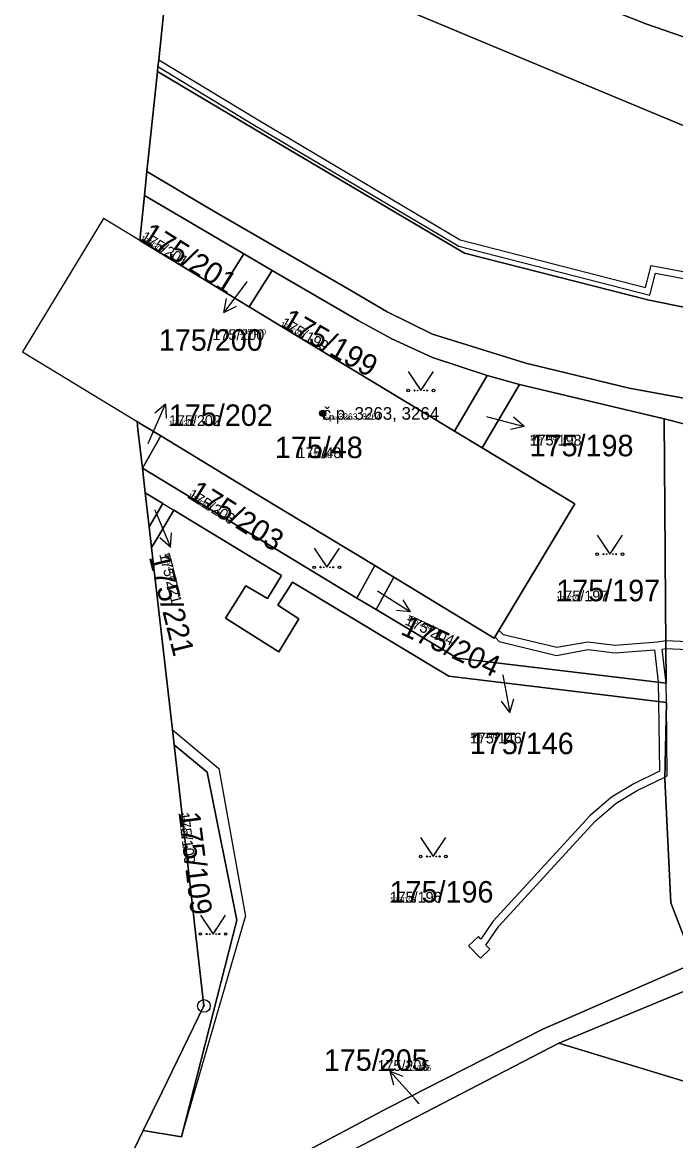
# Model space of a CAD drawing. Extents: x -759873 to -758487, y -975024 to -973516.
# Drawn here: x -759757.9 to -759706.2, y -974666.3 to -974577.8 of the extents above; entities that cross this region are included whole.
import ezdxf

# ---------------------------------------------------------------- set-up
doc = ezdxf.new("R2010")
doc.units = 0
for name, color, linetype in [('KAT_01_hranice KU', 7, 'Continuous'), ('KAT_02_hranice parcel', 7, 'Continuous'), ('KAT_03_1000_st čísla parcelní', 7, 'Continuous'), ('KAT_03_1000_čísla parcelní', 7, 'Continuous'), ('KAT_03_1000_čísla popisná', 7, 'Continuous'), ('KAT_03_250_st čísla parcelní', 7, 'Continuous'), ('KAT_03_250_čísla parcelní', 7, 'Continuous'), ('KAT_03_250_čísla popisná', 7, 'Continuous'), ('KAT_03_500_st čísla parcelní', 7, 'Continuous'), ('KAT_03_500_čísla parcelní', 7, 'Continuous'), ('KAT_03_500_čísla popisná', 7, 'Continuous'), ('KAT_04_vnitřní kresba', 7, 'Continuous'), ('KAT_05_1000_značky kultur', 7, 'Continuous'), ('KAT_05_250_značky kultur', 7, 'Continuous'), ('KAT_05_500_značky kultur', 7, 'Continuous'), ('KAT_07_1000_značky budov', 7, 'Continuous'), ('KAT_07_250_značky budov', 7, 'Continuous'), ('KAT_07_500_značky budov', 7, 'Continuous'), ('KAT_10_věcná břemena', 7, 'Continuous'), ('KAT_11_značky bodu BP', 7, 'Continuous'), ('KAT_12_pomocná šipka', 7, 'Continuous'), ('KAT_14_plocha_budovy', 7, 'Continuous'), ('KAT_14_plocha_pozemek', 7, 'Continuous')]:
    doc.layers.add(name, color=color, linetype=linetype)

msp = doc.modelspace()

# ---------------------------------------------------------------- linework, layer by layer
at = {"layer": 'KAT_01_hranice KU'}
msp.add_lwpolyline([(-759745.87, -974569.1), (-759747.08, -974580.72), (-759747.14, -974581.27), (-759747.18, -974581.65), (-759748.01, -974589.58), (-759748.21, -974591.46), (-759748.58, -974595.04), (-759751.46, -974593.29), (-759757.87, -974603.85), (-759748.79, -974609.36), (-759748.72, -974610), (-759748.37, -974613.06), (-759748.14, -974615.02), (-759747.83, -974617.71), (-759747.65, -974619.33), (-759746, -974633.78), (-759745.86, -974634.95), (-759743.5, -974655.62), (-759746.84, -974662.48), (-759747.59, -974664.02), (-759748.3, -974665.48), (-759749.65, -974668.28)], dxfattribs=at)
at = {"layer": 'KAT_02_hranice parcel'}
for p, q in [((-759748.01, -974589.58), (-759747.18, -974581.65)), ((-759748.21, -974591.46), (-759748.01, -974589.58)), ((-759748.58, -974595.04), (-759748.21, -974591.46)), ((-759748.21, -974591.46), (-759740.34, -974596.08)), ((-759751.46, -974593.29), (-759757.87, -974603.85)), ((-759748.58, -974595.04), (-759751.46, -974593.29)), ((-759742.14, -974598.94), (-759748.58, -974595.04)), ((-759740.34, -974596.08), (-759742.14, -974598.94)), ((-759740.34, -974596.08), (-759738.11, -974597.4)), ((-759738.11, -974597.4), (-759739.92, -974600.29)), ((-759739.92, -974600.29), (-759742.14, -974598.94)), ((-759757.87, -974603.85), (-759748.79, -974609.36)), ((-759721.07, -974605.73), (-759723.67, -974610.12)), ((-759718.53, -974606.42), (-759721.49, -974611.44)), ((-759721.07, -974605.73), (-759718.53, -974606.42)), ((-759718.53, -974606.42), (-759707.06, -974609.14)), ((-759707.06, -974609.14), (-759705.42, -974609.56)), ((-759748.37, -974613.06), (-759746.92, -974610.5)), ((-759721.49, -974611.44), (-759723.67, -974610.12)), ((-759731.41, -974623.34), (-759748.37, -974613.06)), ((-759748.14, -974615.02), (-759748.37, -974613.06)), ((-759747.83, -974617.71), (-759748.14, -974615.02)), ((-759747.65, -974619.33), (-759747.83, -974617.71)), ((-759746, -974633.78), (-759747.65, -974619.33)), ((-759731.41, -974623.34), (-759729.98, -974620.77)), ((-759729.98, -974620.77), (-759728.46, -974621.69)), ((-759728.46, -974621.69), (-759729.87, -974624.24)), ((-759729.87, -974624.24), (-759731.41, -974623.34)), ((-759745.86, -974634.95), (-759746, -974633.78)), ((-759702.4, -974662.54), (-759715.4, -974658.58)), ((-759749.65, -974668.28), (-759748.3, -974665.48))]:
    msp.add_line(p, q, dxfattribs=at)
for points in [[(-759745.19, -974562.55), (-759740.43, -974566.11), (-759725.32, -974571.2), (-759708.52, -974577.87), (-759697.61, -974581.66), (-759664.15, -974586.53), (-759642.54, -974589.75), (-759622.82, -974591), (-759601.22, -974591.07), (-759588.97, -974591.35), (-759580.29, -974589.86), (-759566.46, -974586.39), (-759552.88, -974583.63), (-759547.64, -974583.57)], [(-759747.18, -974581.65), (-759747.14, -974581.27), (-759747.08, -974580.72), (-759745.87, -974569.1)], [(-759745.87, -974569.1), (-759700, -974588.25), (-759649.5, -974597.3), (-759602.4, -974597), (-759547.6, -974592.2), (-759547.08, -974592.24)], [(-759747.18, -974581.65), (-759739.5, -974586.23), (-759722.87, -974596.03), (-759708.27, -974599.76), (-759702.25, -974600.96), (-759687.1, -974602.03), (-759663.8, -974603.29), (-759645.06, -974604.23), (-759636.24, -974604.67), (-759636.23, -974604.2), (-759636.16, -974602.4), (-759636.52, -974602.38), (-759636.5, -974601.88), (-759636.4, -974600.27), (-759636.59, -974600.26), (-759636.49, -974598.18), (-759625.38, -974598.56), (-759610.38, -974599.11), (-759596.55, -974599.59)], [(-759748.01, -974589.58), (-759742.78, -974592.68), (-759732.01, -974598.91), (-759728.99, -974600.68), (-759725.4, -974602.45), (-759718.02, -974604.75), (-759709.84, -974606.71), (-759702.63, -974608.03), (-759689.82, -974608.95), (-759677.23, -974609.87), (-759664.06, -974610.49), (-759641.64, -974611.43), (-759620.48, -974612.36), (-759598.5, -974613.15), (-759577.03, -974613.93), (-759558.28, -974614.4), (-759534.22, -974615.1), (-759512.72, -974615.61), (-759490.5, -974616.02), (-759471.82, -974616.25), (-759458.92, -974616), (-759446.09, -974615.46)], [(-759738.11, -974597.4), (-759731.29, -974601.36), (-759728.62, -974602.81), (-759725.41, -974604.3), (-759721.07, -974605.73)], [(-759723.67, -974610.12), (-759732.79, -974604.61), (-759739.92, -974600.29)], [(-759707.06, -974609.14), (-759707, -974619.81), (-759706.96, -974623.84), (-759706.91, -974630.08), (-759723.46, -974628.1), (-759729.87, -974624.24)], [(-759748.79, -974609.36), (-759748.47, -974609.56), (-759746.92, -974610.5)], [(-759748.37, -974613.06), (-759748.72, -974610), (-759748.79, -974609.36)], [(-759746.92, -974610.5), (-759739.2, -974615.18), (-759729.98, -974620.77)], [(-759728.46, -974621.69), (-759720.53, -974626.5), (-759714.13, -974615.89), (-759721.49, -974611.44)], [(-759748.14, -974615.02), (-759746.75, -974615.85), (-759747.83, -974617.71)], [(-759747.65, -974619.33), (-759747.18, -974618.58), (-759745.89, -974616.37), (-759737.35, -974621.56), (-759738.48, -974623.37), (-759740.17, -974622.36), (-759741.79, -974624.94), (-759737.57, -974627.58), (-759735.99, -974624.98), (-759737.64, -974623.91), (-759736.49, -974622.08), (-759724.11, -974629.53), (-759706.9, -974631.61), (-759707.03, -974637.67), (-759706.54, -974647.47), (-759704.69, -974652.23)], [(-759748.3, -974665.48), (-759745.28, -974665.99), (-759740.9, -974648.84), (-759743.24, -974637.11), (-759745.86, -974634.95)], [(-759746.84, -974662.48), (-759743.5, -974655.62), (-759745.86, -974634.95)], [(-759715.4, -974658.58), (-759700.76, -974652.49), (-759684.23, -974647.96), (-759662.52, -974646.3), (-759662.17, -974641.26), (-759630.55, -974642.48), (-759594.91, -974643.96), (-759576.85, -974644.52), (-759577.12, -974649.37), (-759571.57, -974649.69)], [(-759747.95, -974673.79), (-759728.92, -974663.7), (-759716.68, -974657.46), (-759704.69, -974652.23)], [(-759715.4, -974658.58), (-759733.05, -974667.73), (-759745.1, -974674.23), (-759747.28, -974674.58), (-759747.95, -974673.79)], [(-759748.3, -974665.48), (-759747.59, -974664.02), (-759746.84, -974662.48)]]:
    msp.add_lwpolyline(points, dxfattribs=at)
at = {"layer": 'KAT_03_1000_čísla popisná'}
msp.add_circle((-759734.1, -974608.72), 0.25, dxfattribs=at)
at = {"layer": 'KAT_03_250_čísla popisná'}
msp.add_circle((-759734.1, -974608.72), 0.0625, dxfattribs=at)
at = {"layer": 'KAT_03_500_čísla popisná'}
msp.add_circle((-759734.1, -974608.72), 0.125, dxfattribs=at)
at = {"layer": 'KAT_04_vnitřní kresba'}
for p, q in [((-759747.08, -974580.72), (-759739.22, -974585.49)), ((-759747.14, -974581.27), (-759739.48, -974585.92)), ((-759739.48, -974585.92), (-759723.33, -974595.47)), ((-759739.22, -974585.49), (-759723.21, -974594.99)), ((-759723.21, -974594.99), (-759708.56, -974598.76)), ((-759723.33, -974595.47), (-759708.2, -974599.37)), ((-759708.56, -974598.76), (-759708.11, -974597.02)), ((-759708.2, -974599.37), (-759707.75, -974597.63)), ((-759708.11, -974597.02), (-759701.56, -974598.24)), ((-759707.75, -974597.63), (-759702.1, -974598.7)), ((-759746.75, -974615.85), (-759745.89, -974616.37)), ((-759746, -974633.78), (-759742.32, -974636.83)), ((-759742.32, -974636.83), (-759740.21, -974648.55)), ((-759745.28, -974665.99), (-759740.21, -974648.55))]:
    msp.add_line(p, q, dxfattribs=at)
at = {"layer": 'KAT_05_1000_značky kultur'}
for points in [[(-759727.33, -974605.409), (-759726.33, -974606.91), (-759725.33, -974605.409)], [(-759712.37, -974618.359), (-759711.37, -974619.86), (-759710.37, -974618.359)], [(-759734.77, -974619.399), (-759733.77, -974620.9), (-759732.77, -974619.399)], [(-759726.35, -974642.289), (-759725.35, -974643.79), (-759724.35, -974642.289)], [(-759743.78, -974648.429), (-759742.78, -974649.93), (-759741.78, -974648.429)]]:
    msp.add_lwpolyline(points, dxfattribs=at)
for centre in [(-759727.33, -974606.909), (-759725.33, -974606.909), (-759712.37, -974619.859), (-759710.37, -974619.859), (-759734.77, -974620.899), (-759732.77, -974620.899), (-759726.35, -974643.789), (-759724.35, -974643.789), (-759743.78, -974649.929), (-759741.78, -974649.929)]:
    msp.add_circle(centre, 0.1, dxfattribs=at)
at = {"layer": 'KAT_05_250_značky kultur'}
for points in [[(-759726.58, -974606.535), (-759726.33, -974606.91), (-759726.08, -974606.535)], [(-759711.62, -974619.485), (-759711.37, -974619.86), (-759711.12, -974619.485)], [(-759734.02, -974620.525), (-759733.77, -974620.9), (-759733.52, -974620.525)], [(-759725.6, -974643.415), (-759725.35, -974643.79), (-759725.1, -974643.415)], [(-759743.03, -974649.555), (-759742.78, -974649.93), (-759742.53, -974649.555)]]:
    msp.add_lwpolyline(points, dxfattribs=at)
for centre in [(-759726.58, -974606.91), (-759726.08, -974606.91), (-759711.62, -974619.86), (-759711.12, -974619.86), (-759734.02, -974620.9), (-759733.52, -974620.9), (-759725.6, -974643.79), (-759725.1, -974643.79), (-759743.03, -974649.93), (-759742.53, -974649.93)]:
    msp.add_circle(centre, 0.025, dxfattribs=at)
at = {"layer": 'KAT_05_500_značky kultur'}
for points in [[(-759726.83, -974606.16), (-759726.33, -974606.91), (-759725.83, -974606.16)], [(-759711.87, -974619.11), (-759711.37, -974619.86), (-759710.87, -974619.11)], [(-759734.27, -974620.15), (-759733.77, -974620.9), (-759733.27, -974620.15)], [(-759725.85, -974643.04), (-759725.35, -974643.79), (-759724.85, -974643.04)], [(-759743.28, -974649.179), (-759742.78, -974649.93), (-759742.28, -974649.179)]]:
    msp.add_lwpolyline(points, dxfattribs=at)
for centre in [(-759726.83, -974606.91), (-759725.83, -974606.91), (-759711.87, -974619.86), (-759710.87, -974619.86), (-759734.27, -974620.9), (-759733.27, -974620.9), (-759725.85, -974643.79), (-759724.85, -974643.79), (-759743.28, -974649.93), (-759742.28, -974649.93)]:
    msp.add_circle(centre, 0.05, dxfattribs=at)
at = {"layer": 'KAT_07_1000_značky budov'}
msp.add_circle((-759734.107, -974608.719), 0.175, dxfattribs=at)
at = {"layer": 'KAT_07_250_značky budov'}
msp.add_circle((-759734.102, -974608.72), 0.0437, dxfattribs=at)
at = {"layer": 'KAT_07_500_značky budov'}
msp.add_circle((-759734.103, -974608.72), 0.0875, dxfattribs=at)
at = {"layer": 'KAT_10_věcná břemena'}
msp.add_lwpolyline([(-759705.2, -974626.81), (-759706.94, -974626.72), (-759707.61, -974626.82), (-759710.96, -974627.08), (-759713.11, -974626.82), (-759715.57, -974627.26), (-759719.8, -974626.24), (-759720.15, -974625.87), (-759720.47, -974626.4), (-759720.12, -974626.78), (-759715.59, -974627.88), (-759713.09, -974627.42), (-759710.98, -974627.68), (-759707.83, -974627.44), (-759707.55, -974630), (-759707.52, -974631.53), (-759707.43, -974637.04), (-759709.48, -974638.04), (-759711.24, -974639.1), (-759712.96, -974640.57), (-759720.63, -974648.93), (-759721.59, -974650.34), (-759721.78, -974650.12), (-759722.56, -974650.87), (-759721.61, -974651.85), (-759720.87, -974651.13), (-759721.18, -974650.8), (-759720.15, -974649.31), (-759712.54, -974641.01), (-759710.88, -974639.58), (-759709.2, -974638.56), (-759707.03, -974637.51), (-759706.83, -974637.42), (-759706.9, -974631.61), (-759706.91, -974630.08), (-759707.24, -974627.37), (-759706.93, -974627.32), (-759705.19, -974627.41)], dxfattribs=at)
at = {"layer": 'KAT_11_značky bodu BP'}
for radius in [0.5, 0.0303]:
    msp.add_circle((-759743.5, -974655.62), radius, dxfattribs=at)
at = {"layer": 'KAT_12_pomocná šipka'}
for p, q in [((-759740.12, -974598.33), (-759741.926, -974600.727)), ((-759740.08, -974598.28), (-759740.12, -974598.33)), ((-759741.926, -974600.727), (-759741.723, -974599.626)), ((-759741.926, -974600.727), (-759740.923, -974600.228)), ((-759747.75, -974610.73), (-759746.529, -974607.988)), ((-759746.529, -974607.988), (-759747.394, -974608.7)), ((-759746.529, -974607.988), (-759746.479, -974609.107)), ((-759721.14, -974608.97), (-759721.05, -974608.99)), ((-759721.05, -974608.99), (-759718.151, -974609.767)), ((-759718.151, -974609.767), (-759718.989, -974609.024)), ((-759718.151, -974609.767), (-759719.248, -974609.991)), ((-759747.91, -974611.1), (-759747.75, -974610.73)), ((-759747.4, -974616.32), (-759747.31, -974616.54)), ((-759747.31, -974616.54), (-759746.137, -974619.302)), ((-759746.137, -974619.302), (-759746.99, -974618.576)), ((-759746.137, -974619.302), (-759746.068, -974618.185)), ((-759729.79, -974622.77), (-759729.69, -974622.83)), ((-759729.69, -974622.83), (-759727.145, -974624.42)), ((-759727.145, -974624.42), (-759727.729, -974623.465)), ((-759727.145, -974624.42), (-759728.26, -974624.314)), ((-759719.86, -974629.4), (-759719.85, -974629.44)), ((-759719.85, -974629.44), (-759719.277, -974632.386)), ((-759719.277, -974632.386), (-759719.96, -974631.498)), ((-759719.277, -974632.386), (-759718.977, -974631.307)), ((-759726.79, -974663.01), (-759728.798, -974660.78)), ((-759728.798, -974660.78), (-759727.756, -974661.189)), ((-759728.798, -974660.78), (-759728.5, -974661.859)), ((-759726.46, -974663.38), (-759726.79, -974663.01))]:
    msp.add_line(p, q, dxfattribs=at)
at = {"layer": 'KAT_14_plocha_budovy'}
msp.add_lwpolyline([(-759728.46, -974621.69), (-759720.53, -974626.5), (-759714.13, -974615.89), (-759721.49, -974611.44), (-759723.67, -974610.12), (-759732.79, -974604.61), (-759739.92, -974600.29), (-759742.14, -974598.94), (-759748.58, -974595.04), (-759751.46, -974593.29), (-759757.87, -974603.85), (-759748.79, -974609.36), (-759748.47, -974609.56), (-759746.92, -974610.5), (-759739.2, -974615.18), (-759729.98, -974620.77)], close=True, dxfattribs=at)
at = {"layer": 'KAT_14_plocha_pozemek'}
for points in [[(-759601.22, -974591.07), (-759588.97, -974591.35), (-759580.29, -974589.86), (-759566.46, -974586.39), (-759552.88, -974583.63), (-759547.64, -974583.57), (-759550.22, -974544.33), (-759551.48, -974544.27), (-759563.58, -974549.84), (-759564.84, -974554.11), (-759642.97, -974554.16), (-759688.61, -974551.58), (-759703.8, -974545.25), (-759742.76, -974539.26), (-759745.19, -974562.55), (-759740.43, -974566.11), (-759725.32, -974571.2), (-759708.52, -974577.87), (-759697.61, -974581.66), (-759664.15, -974586.53), (-759642.54, -974589.75), (-759622.82, -974591)], [(-759547.08, -974592.24), (-759547.64, -974583.57), (-759552.88, -974583.63), (-759566.46, -974586.39), (-759580.29, -974589.86), (-759588.97, -974591.35), (-759601.22, -974591.07), (-759622.82, -974591), (-759642.54, -974589.75), (-759664.15, -974586.53), (-759697.61, -974581.66), (-759708.52, -974577.87), (-759725.32, -974571.2), (-759740.43, -974566.11), (-759745.19, -974562.55), (-759745.87, -974569.1), (-759700, -974588.25), (-759649.5, -974597.3), (-759602.4, -974597), (-759547.6, -974592.2)], [(-759748.21, -974591.46), (-759748.58, -974595.04), (-759742.14, -974598.94), (-759740.34, -974596.08)], [(-759720.53, -974626.5), (-759714.13, -974615.89), (-759721.49, -974611.44), (-759723.67, -974610.12), (-759732.79, -974604.61), (-759739.92, -974600.29), (-759742.14, -974598.94), (-759748.58, -974595.04), (-759751.46, -974593.29), (-759757.87, -974603.85), (-759748.79, -974609.36), (-759748.47, -974609.56), (-759746.92, -974610.5), (-759739.2, -974615.18), (-759729.98, -974620.77), (-759728.46, -974621.69)], [(-759738.11, -974597.4), (-759740.34, -974596.08), (-759742.14, -974598.94), (-759739.92, -974600.29)], [(-759721.07, -974605.73), (-759725.41, -974604.3), (-759728.62, -974602.81), (-759731.29, -974601.36), (-759738.11, -974597.4), (-759739.92, -974600.29), (-759732.79, -974604.61), (-759723.67, -974610.12)], [(-759721.49, -974611.44), (-759714.13, -974615.89), (-759720.53, -974626.5), (-759728.46, -974621.69), (-759729.87, -974624.24), (-759723.46, -974628.1), (-759706.91, -974630.08), (-759706.96, -974623.84), (-759707, -974619.81), (-759707.06, -974609.14), (-759718.53, -974606.42)], [(-759721.49, -974611.44), (-759718.53, -974606.42), (-759721.07, -974605.73), (-759723.67, -974610.12)], [(-759746.92, -974610.5), (-759748.47, -974609.56), (-759748.79, -974609.36), (-759748.72, -974610), (-759748.37, -974613.06)], [(-759748.37, -974613.06), (-759731.41, -974623.34), (-759729.98, -974620.77), (-759739.2, -974615.18), (-759746.92, -974610.5)], [(-759747.83, -974617.71), (-759746.75, -974615.85), (-759748.14, -974615.02)], [(-759729.87, -974624.24), (-759728.46, -974621.69), (-759729.98, -974620.77), (-759731.41, -974623.34)], [(-759743.5, -974655.62), (-759746.84, -974662.48), (-759747.59, -974664.02), (-759748.3, -974665.48), (-759745.28, -974665.99), (-759740.9, -974648.84), (-759743.24, -974637.11), (-759745.86, -974634.95)]]:
    msp.add_lwpolyline(points, close=True, dxfattribs=at)
for points in [[(-759700, -974588.25), (-759745.87, -974569.1), (-759747.08, -974580.72), (-759747.14, -974581.27), (-759747.18, -974581.65), (-759739.5, -974586.23), (-759722.87, -974596.03), (-759708.27, -974599.76), (-759702.25, -974600.96)], [(-759702.25, -974600.96), (-759708.27, -974599.76), (-759722.87, -974596.03), (-759739.5, -974586.23), (-759747.18, -974581.65), (-759748.01, -974589.58), (-759742.78, -974592.68), (-759732.01, -974598.91), (-759728.99, -974600.68), (-759725.4, -974602.45), (-759718.02, -974604.75), (-759709.84, -974606.71), (-759702.63, -974608.03)], [(-759702.63, -974608.03), (-759709.84, -974606.71), (-759718.02, -974604.75), (-759725.4, -974602.45), (-759728.99, -974600.68), (-759732.01, -974598.91), (-759742.78, -974592.68), (-759748.01, -974589.58), (-759748.21, -974591.46), (-759740.34, -974596.08), (-759738.11, -974597.4), (-759731.29, -974601.36), (-759728.62, -974602.81), (-759725.41, -974604.3), (-759721.07, -974605.73), (-759718.53, -974606.42), (-759707.06, -974609.14), (-759705.42, -974609.56)], [(-759705.42, -974609.56), (-759707.06, -974609.14), (-759707, -974619.81), (-759706.96, -974623.84), (-759706.91, -974630.08), (-759723.46, -974628.1), (-759729.87, -974624.24), (-759731.41, -974623.34), (-759748.37, -974613.06), (-759748.14, -974615.02), (-759746.75, -974615.85), (-759747.83, -974617.71), (-759747.65, -974619.33), (-759747.18, -974618.58), (-759745.89, -974616.37), (-759737.35, -974621.56), (-759738.48, -974623.37)], [(-759747.95, -974673.79), (-759728.92, -974663.7), (-759716.68, -974657.46), (-759704.69, -974652.23), (-759706.54, -974647.47), (-759707.03, -974637.67), (-759706.9, -974631.61), (-759724.11, -974629.53), (-759736.49, -974622.08), (-759737.64, -974623.91), (-759735.99, -974624.98), (-759737.57, -974627.58), (-759741.79, -974624.94), (-759740.17, -974622.36), (-759738.48, -974623.37), (-759737.35, -974621.56), (-759745.89, -974616.37), (-759747.18, -974618.58), (-759747.65, -974619.33), (-759746, -974633.78), (-759745.86, -974634.95), (-759743.24, -974637.11), (-759740.9, -974648.84), (-759745.28, -974665.99), (-759748.3, -974665.48), (-759749.65, -974668.28)], [(-759738.48, -974623.37), (-759740.17, -974622.36), (-759741.79, -974624.94), (-759737.57, -974627.58), (-759735.99, -974624.98), (-759737.64, -974623.91), (-759736.49, -974622.08), (-759724.11, -974629.53), (-759706.9, -974631.61), (-759707.03, -974637.67), (-759706.54, -974647.47), (-759704.69, -974652.23)], [(-759595.23, -974642.21), (-759608.85, -974641.69), (-759610.85, -974641.63), (-759629.88, -974640.85), (-759637.61, -974640.58), (-759639.42, -974640.48), (-759662.12, -974639.59), (-759663.72, -974639.51), (-759664.13, -974644.65), (-759682.14, -974645.97), (-759685.62, -974646.56), (-759701.34, -974650.97), (-759703.01, -974651.57), (-759704.69, -974652.23), (-759716.68, -974657.46), (-759728.92, -974663.7), (-759747.95, -974673.79)], [(-759733.05, -974667.73), (-759715.4, -974658.58), (-759700.76, -974652.49), (-759684.23, -974647.96), (-759662.52, -974646.3), (-759662.17, -974641.26), (-759630.55, -974642.48), (-759594.91, -974643.96)], [(-759594.91, -974643.96), (-759630.55, -974642.48), (-759662.17, -974641.26), (-759662.52, -974646.3), (-759684.23, -974647.96), (-759700.76, -974652.49), (-759715.4, -974658.58), (-759702.4, -974662.54), (-759697.41, -974659.37), (-759686.46, -974655.24), (-759683.19, -974654.36), (-759662.83, -974651.97), (-759662.89, -974653.64), (-759663.1, -974657.24), (-759609.55, -974659.41), (-759577.87, -974660.7)], [(-759604.43, -974666.7), (-759628.9, -974665.77), (-759647.86, -974664.97), (-759691.51, -974663.12), (-759700.72, -974662.63), (-759702.4, -974662.54), (-759715.4, -974658.58), (-759733.05, -974667.73)]]:
    msp.add_lwpolyline(points, dxfattribs=at)

# ---------------------------------------------------------------- texts
at = {"layer": 'KAT_03_1000_st čísla parcelní'}
msp.add_text('175/48', height=1.7, dxfattribs=at).set_placement((-759737.885, -974612.26))
at = {"layer": 'KAT_03_1000_čísla parcelní'}
for s, rotation, p in [('175/201', 328, (-759748.58, -974594.96)), ('175/199', 330, (-759737.515, -974601.796)), ('175/203', 328, (-759744.86, -974615.36)), ('175/221', 284, (-759747.869, -974620.075)), ('175/204', 335, (-759728.017, -974626.167)), ('175/109', 277, (-759745.513, -974640.343))]:
    msp.add_text(s, height=1.7, rotation=rotation, dxfattribs=at).set_placement(p)
for s, p in [('175/200', (-759747.066, -974603.763)), ('175/202', (-759746.27, -974609.71)), ('175/198', (-759717.72, -974612.113)), ('175/197', (-759715.61, -974623.59)), ('175/146', (-759722.45, -974635.693)), ('175/196', (-759728.8, -974647.44)), ('175/205', (-759734.006, -974660.76))]:
    msp.add_text(s, height=1.7, dxfattribs=at).set_placement(p)
at = {"layer": 'KAT_03_1000_čísla popisná'}
msp.add_text('č.p. 3263, 3264', height=1, dxfattribs=at).set_placement((-759734.1, -974609.22))
at = {"layer": 'KAT_03_250_st čísla parcelní'}
msp.add_text('175/48', height=0.425, dxfattribs=at).set_placement((-759735.201, -974612.26))
at = {"layer": 'KAT_03_250_čísla parcelní'}
for s, rotation, p in [('175/201', 328, (-759748.58, -974594.96)), ('175/199', 330, (-759737.515, -974601.796)), ('175/203', 328, (-759744.86, -974615.36)), ('175/221', 284, (-759746.632, -974619.767)), ('175/204', 335, (-759727.478, -974625.011)), ('175/109', 277, (-759745.513, -974640.343))]:
    msp.add_text(s, height=0.425, rotation=rotation, dxfattribs=at).set_placement(p)
for s, p in [('175/200', (-759740.715, -974602.488)), ('175/202', (-759746.27, -974609.71)), ('175/198', (-759717.72, -974610.838)), ('175/197', (-759715.61, -974623.59)), ('175/146', (-759722.45, -974634.418)), ('175/196', (-759728.8, -974647.44)), ('175/205', (-759727.641, -974660.76))]:
    msp.add_text(s, height=0.425, dxfattribs=at).set_placement(p)
at = {"layer": 'KAT_03_250_čísla popisná'}
msp.add_text('č.p. 3263, 3264', height=0.25, dxfattribs=at).set_placement((-759734.1, -974609.22))
at = {"layer": 'KAT_03_500_st čísla parcelní'}
msp.add_text('175/48', height=0.85, dxfattribs=at).set_placement((-759736.096, -974612.26))
at = {"layer": 'KAT_03_500_čísla parcelní'}
for s, rotation, p in [('175/201', 328, (-759748.58, -974594.96)), ('175/199', 330, (-759737.515, -974601.796)), ('175/203', 328, (-759744.86, -974615.36)), ('175/221', 284, (-759747.044, -974619.869)), ('175/204', 335, (-759727.658, -974625.397)), ('175/109', 277, (-759745.513, -974640.343))]:
    msp.add_text(s, height=0.85, rotation=rotation, dxfattribs=at).set_placement(p)
for s, p in [('175/200', (-759742.832, -974602.913)), ('175/202', (-759746.27, -974609.71)), ('175/198', (-759717.72, -974611.263)), ('175/197', (-759715.61, -974623.59)), ('175/146', (-759722.45, -974634.843)), ('175/196', (-759728.8, -974647.44)), ('175/205', (-759729.762, -974660.76))]:
    msp.add_text(s, height=0.85, dxfattribs=at).set_placement(p)
at = {"layer": 'KAT_03_500_čísla popisná'}
msp.add_text('č.p. 3263, 3264', height=0.5, dxfattribs=at).set_placement((-759734.1, -974609.22))

doc.saveas('drawing.dxf')
